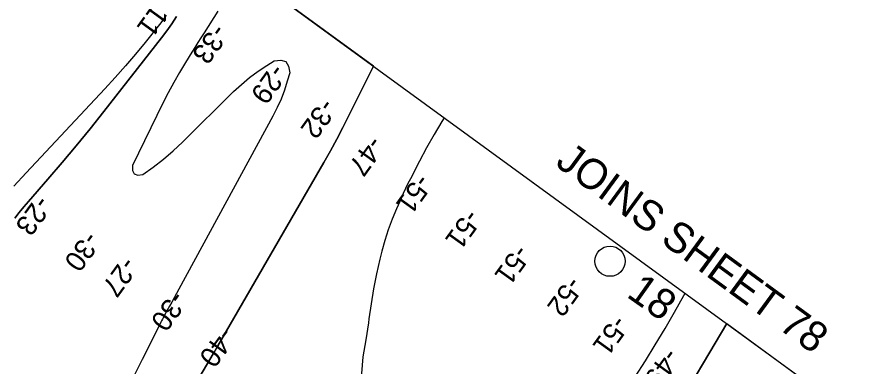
# Model space of a CAD drawing. Extents: x 3879599 to 3900814, y 146526 to 168888.
# Drawn here: x 3895080 to 3896475, y 161997 to 162574 of the extents above; entities that cross this region are included whole.
import ezdxf

# ---------------------------------------------------------------- set-up
doc = ezdxf.new("R2010")
doc.units = 0
for name, color, linetype in [('V-ANNO-TEXT', 7, 'Continuous'), ('V-GRID-FRAM', 7, 'Continuous'), ('V-RIVR-IDEN', 7, 'Continuous'), ('V-RIVR-MILE', 7, 'Continuous'), ('V-RIVR-RANG', 7, 'Continuous'), ('V-TOPO-DPTH', 7, 'Continuous'), ('V-TOPO-MAJR', 7, 'Continuous'), ('V-TOPO-MINR', 7, 'Continuous')]:
    doc.layers.add(name, color=color, linetype=linetype)

msp = doc.modelspace()

# ---------------------------------------------------------------- linework, layer by layer
at = {"layer": 'V-GRID-FRAM'}
msp.add_lwpolyline([(3898776.6, 160226.4), (3889730.7, 148455.2), (3882888.9, 153284.4), (3891901.5, 165241.3), (3898776.6, 160226.4)], dxfattribs=at)
at = {"layer": 'V-RIVR-MILE'}
msp.add_circle((3896060.5, 162170.1), 25, dxfattribs=at)
at = {"layer": 'V-TOPO-DPTH'}
for p, q in [((3895669.6, 162492.7), (3895455, 162649.3)), ((3896253.5, 162066.8), (3896422, 161943.9))]:
    msp.add_line(p, q, dxfattribs=at)
for points in [[(3895412.1, 162583.5), (3895389.6, 162547.9), (3895384.5, 162539.9), (3895379.5, 162531.9), (3895374.4, 162523.8), (3895369.4, 162515.7), (3895359.1, 162499), (3895349.1, 162482.5), (3895339.5, 162465.7), (3895330.5, 162448.7), (3895321.7, 162431.5), (3895271.3, 162328.2), (3895271.6, 162320), (3895274.1, 162314.4), (3895280, 162312.6), (3895288.2, 162313.5), (3895305.5, 162325.8), (3895322.4, 162338.8), (3895338.5, 162352.7), (3895354.1, 162367.3), (3895438.4, 162450.8), (3895451.3, 162462.7), (3895464.7, 162474), (3895478.8, 162484.3), (3895493.4, 162494), (3895505.2, 162501.4), (3895516.5, 162502.7), (3895525, 162500.4), (3895529.4, 162492.8), (3895531.2, 162481.6), (3895527.1, 162467.9), (3895522.3, 162453.1), (3895516.8, 162438.4), (3895510.3, 162424.2), (3895503.3, 162410.2), (3895347.8, 162123.6), (3895344, 162116.6), (3895340.1, 162109.6), (3895336.3, 162102.6), (3895332.4, 162095.6), (3895326.1, 162084.2), (3895324.1, 162080.4), (3895323.4, 162079.1), (3895322.1, 162076.6), (3895320.8, 162074.1), (3895319.5, 162071.6), (3895318.2, 162069.1), (3895317, 162066.6), (3895287.3, 162007.6), (3895271.1, 161975.6)], [(3895412.1, 162583.5), (3895389.6, 162547.9), (3895384.5, 162539.9), (3895379.5, 162531.9), (3895374.4, 162523.8), (3895369.4, 162515.7), (3895359.1, 162499), (3895349.1, 162482.5), (3895339.5, 162465.7), (3895330.5, 162448.7), (3895321.7, 162431.5), (3895271.3, 162328.2), (3895271.6, 162320), (3895274.1, 162314.4), (3895280, 162312.6), (3895288.2, 162313.5), (3895305.5, 162325.8), (3895322.4, 162338.8), (3895338.5, 162352.7), (3895354.1, 162367.3), (3895438.4, 162450.8), (3895451.3, 162462.7), (3895464.7, 162474), (3895478.8, 162484.3), (3895493.4, 162494), (3895505.2, 162501.4), (3895516.5, 162502.7), (3895525, 162500.4), (3895529.4, 162492.8), (3895531.2, 162481.6), (3895527.1, 162467.9), (3895522.3, 162453.1), (3895516.8, 162438.4), (3895510.3, 162424.2), (3895503.3, 162410.2), (3895347.8, 162123.6), (3895344, 162116.6), (3895340.1, 162109.6), (3895336.3, 162102.6), (3895332.4, 162095.6), (3895326.1, 162084.2), (3895324.1, 162080.4), (3895323.4, 162079.1), (3895322.1, 162076.6), (3895320.8, 162074.1), (3895319.5, 162071.6), (3895318.2, 162069.1), (3895317, 162066.6), (3895287.3, 162007.6), (3895271.1, 161975.6)], [(3895344.2, 162575), (3895336.4, 162562.9), (3895328, 162551.1), (3895319.4, 162539.5), (3895223.9, 162417.7), (3895201.3, 162389.3), (3895178.4, 162361.1), (3895155.1, 162333.3), (3895131.5, 162305.8), (3895099.4, 162268.8), (3895091.8, 162259.8), (3895084.3, 162250.6), (3895077.1, 162241.3)], [(3895077.1, 162241.3), (3895084.3, 162250.6), (3895091.8, 162259.8), (3895099.4, 162268.8), (3895131.5, 162305.8), (3895155.1, 162333.3), (3895178.4, 162361.1), (3895201.3, 162389.3), (3895223.9, 162417.7), (3895319.4, 162539.5), (3895328, 162551.1), (3895336.4, 162562.9), (3895344.2, 162575)], [(3894988.9, 161367.9), (3895158.5, 161610.6), (3895181.2, 161644), (3895203.5, 161677.8), (3895224.9, 161712.1), (3895245.8, 161746.7), (3895404.5, 162016.9), (3895405.5, 162018.7), (3895407.7, 162022.5), (3895409.9, 162026.1), (3895411.5, 162028.7), (3895412.3, 162030.1), (3895587.5, 162333.5), (3895598.3, 162352.6), (3895608.9, 162371.9), (3895619.1, 162391.3), (3895629, 162410.9), (3895669.6, 162492.7)], [(3894988.9, 161367.9), (3895158.5, 161610.6), (3895181.2, 161644), (3895203.5, 161677.8), (3895224.9, 161712.1), (3895245.8, 161746.7), (3895404.5, 162016.9), (3895405.5, 162018.7), (3895407.7, 162022.5), (3895409.9, 162026.1), (3895411.5, 162028.7), (3895412.3, 162030.1), (3895587.5, 162333.5), (3895598.3, 162352.6), (3895608.9, 162371.9), (3895619.1, 162391.3), (3895629, 162410.9), (3895669.6, 162492.7)], [(3896201.3, 161979), (3896215.2, 162002.1), (3896253.5, 162066.8)], [(3896253.5, 162066.8), (3896215.2, 162002.1), (3896201.3, 161979)]]:
    msp.add_lwpolyline(points, dxfattribs=at)
at = {"layer": 'V-TOPO-MAJR'}
for points in [[(3895786.4, 162407.5), (3895782.6, 162401.3), (3895769.7, 162379.6), (3895757.4, 162357.6), (3895745.5, 162335.4), (3895730.7, 162306.6), (3895726.6, 162298.6), (3895722.6, 162290.5), (3895718.8, 162282.3), (3895715.1, 162274.1), (3895707.4, 162256.7), (3895700.4, 162239.6), (3895694, 162222.2), (3895688.5, 162204.6), (3895683.5, 162186.8), (3895680.3, 162173.7), (3895674.7, 162149.1), (3895669.6, 162124.4), (3895665.5, 162099.5), (3895661.9, 162074.5), (3895661.1, 162068.2), (3895657, 162040.1), (3895651.9, 162012.1), (3895637, 161827.2)], [(3896102, 161978.8), (3896118.9, 162005.2), (3896135.3, 162031.8), (3896151.5, 162058.7), (3896167.1, 162085.9), (3896182.4, 162113.2), (3896184.5, 162117.2)]]:
    msp.add_lwpolyline(points, dxfattribs=at)
at = {"layer": 'V-TOPO-MINR'}
for points in [[(3895412.1, 162583.5), (3895389.6, 162547.9), (3895384.5, 162539.9), (3895379.5, 162531.9), (3895374.4, 162523.8), (3895369.4, 162515.7), (3895359.1, 162499), (3895349.1, 162482.5), (3895339.5, 162465.7), (3895330.5, 162448.7), (3895321.7, 162431.5), (3895271.3, 162328.2), (3895271.6, 162320), (3895274.1, 162314.4), (3895280, 162312.6), (3895288.2, 162313.5), (3895305.5, 162325.8), (3895322.4, 162338.8), (3895338.5, 162352.7), (3895354.1, 162367.3), (3895438.4, 162450.8), (3895451.3, 162462.7), (3895464.7, 162474), (3895478.8, 162484.3), (3895493.4, 162494), (3895505.2, 162501.4), (3895516.5, 162502.7), (3895525, 162500.4), (3895529.4, 162492.8), (3895531.2, 162481.6), (3895527.1, 162467.9), (3895522.3, 162453.1), (3895516.8, 162438.4), (3895510.3, 162424.2), (3895503.3, 162410.2), (3895347.8, 162123.6), (3895344, 162116.6), (3895340.1, 162109.6), (3895336.3, 162102.6), (3895332.4, 162095.6), (3895326.1, 162084.2), (3895324.1, 162080.4), (3895323.4, 162079.1), (3895322.1, 162076.6), (3895320.8, 162074.1), (3895319.5, 162071.6), (3895318.2, 162069.1), (3895317, 162066.6), (3895287.3, 162007.6), (3895271.1, 161975.6)], [(3895327.2, 162577.4), (3895323.7, 162572), (3895320, 162566.8), (3895316.1, 162561.7), (3895292.3, 162532.1), (3895276.1, 162512.5), (3895259.6, 162493.1), (3895242.7, 162474.1), (3895225.5, 162455.4), (3895095.5, 162316.5), (3895075.2, 162294.2)], [(3895344.2, 162575), (3895336.4, 162562.9), (3895328, 162551.1), (3895319.4, 162539.5), (3895223.9, 162417.7), (3895201.3, 162389.3), (3895178.4, 162361.1), (3895155.1, 162333.3), (3895131.5, 162305.8), (3895099.4, 162268.8), (3895091.8, 162259.8), (3895084.3, 162250.6), (3895077.1, 162241.3)], [(3895669.6, 162492.7), (3895629, 162410.9), (3895619.1, 162391.3), (3895608.9, 162371.9), (3895598.3, 162352.6), (3895587.5, 162333.5), (3895412.3, 162030.1), (3895411.5, 162028.7), (3895409.9, 162026.1), (3895407.7, 162022.5), (3895405.5, 162018.7), (3895404.5, 162016.9), (3895245.8, 161746.7), (3895224.9, 161712.1), (3895203.5, 161677.8), (3895181.2, 161644), (3895158.5, 161610.6), (3894988.9, 161367.9)], [(3896201.3, 161979), (3896215.2, 162002.1), (3896253.5, 162066.8)]]:
    msp.add_lwpolyline(points, dxfattribs=at)

# ---------------------------------------------------------------- texts
at = {"layer": 'V-ANNO-TEXT'}
msp.add_text('JOINS SHEET 78', height=50, rotation=323.7866, dxfattribs=at).set_placement((3895968.2, 162329.4))
at = {"layer": 'V-RIVR-IDEN'}
msp.add_text('18', height=50, rotation=324.748, dxfattribs=at).set_placement((3896086, 162112.3))
at = {"layer": 'V-RIVR-RANG'}
for s, rotation, p in [('-11', 234.0383, (3895315, 162609.6)), ('-33', 234.0383, (3895406.3, 162565.1)), ('-29', 234.1817, (3895503, 162498.9)), ('-32', 234.1817, (3895585.3, 162441.7)), ('-47', 234.1817, (3895664.1, 162379.8)), ('-51', 234.1817, (3895743, 162316.9)), ('-23', 233.9483, (3895114.4, 162281.2)), ('-51', 234.1817, (3895824.3, 162258.4)), ('-30', 233.9483, (3895194.9, 162221.8)), ('-51', 234.1817, (3895905.8, 162199.7)), ('-27', 234.0899, (3895256.5, 162179.8)), ('-52', 234.1817, (3895992.8, 162147.3)), ('-30', 234.0899, (3895337.8, 162123.3)), ('-51', 234.1817, (3896068, 162082.9)), ('-40', 234.0899, (3895417.8, 162063.5)), ('-49', 234.1817, (3896153.2, 162028.7))]:
    msp.add_text(s, height=33.5, rotation=rotation, dxfattribs=at).set_placement(p)

doc.saveas('drawing.dxf')
